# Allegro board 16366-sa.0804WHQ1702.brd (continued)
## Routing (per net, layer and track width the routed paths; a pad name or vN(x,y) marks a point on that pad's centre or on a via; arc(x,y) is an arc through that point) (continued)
P3V3_PG: length 102.1
  TOP w0.178: U9.2 10.9,75.95 12.55,77.6 55.53,77.6 56.23,76.9 56.23,75.89 56.81,75.3 74.46,75.3 79.02,70.75 82.3,70.75 85.22,67.83 97.18,67.83 97.73,68.37 PR441.1 98.56,68.37 99.01,68.82 101.6,68.82 PR2172.2 PR347.2 103.95,68.86 104.67,68.14 PU54.3
P3V3_RF: length 5.1
  TOP w0.254: v2(112.25,73.26) 112.06,73.07 PR3.2 PR4.2 112.06,70.53 111.79,70.27 111.79,69.47 111.46,69.14 PU54.22
P3V3_ROVP: length 4.1
  TOP w0.254: PU54.5 104.89,67.14 v2(104.09,66.34) 102.71,64.96 PR817.1
P3V3_SNB: length 1.7
  TOP w0.254: PC918.2 108.4,60.09 PR642.1
P3V3_TRIP: length 3.9
  TOP w0.254: PR2.2 112.98,70.6 112.98,69.55 v2(112.82,69.4) 112.07,68.64 112.07,68.64 PU54.21
P3V3_VBST: length 3.7
  TOP w0.305: PU54.4 104.23,67.64 103.21,66.61 PR481.1
P3V3_VBST_RC: length 1.2
  TOP w0.508: PC917.1 PR481.2
P3V3_VDD: length 10.3
  TOP w0.305: PC941.1 v2(115.78,70.83) 114.93,69.98 114.93,69.63 112.93,67.64 PU54.19
  TOP w0.508: PR649.2 117.38,69.89 PC941.1
P3V3_VFB: length 10.1
  TOP w0.254: PU54.1 105.87,71.11 106.02,71.26 PR638.1 106.02,72.45 104.75,73.72 PR635.2 PC485.2
P3V3_VFB_R: length 3.2
  TOP w0.254: PR635.1 100.53,73.9 100.53,74.85 v2(100.38,75) 100.1,75 99.39,74.3 99.39,73.87 PR633.2
P3V3_VIN:
  vias: v2(114.72,64.33)
P3V3_VREG: length 34.5
  TOP w0.254: v1(114.89,68.41) 114.89,67.8 PC942.2 114.22,67.14 PU54.18 ; PR441.2 99.01,67.48 v1(99.63,68.1) ; PR3.1 111.17,73 v1(111.18,73.01)
  BOTTOM w0.254: v1(111.18,73.01) 111.51,73.34 113.55,73.34 v2(115.38,71.51) 116.42,70.47 116.42,69.15 115.68,68.41 v1(114.89,68.41) 110.85,68.41 110.34,67.91 105.85,67.91 104.02,66.08 101.65,66.08 v1(99.63,68.1)
P12V: length 91.5
  TOP w0.457: CN2.B1 22.09,51.86 ; CN2.B1 22.98,50.98 ; CN2.B1 21.2,50.98 ; CN2.B1 22.09,50.09 ; CN4.4 119.9,48.24 ; CN4.4 118.26,46.6 ; CN4.4 119.9,44.96 ; CN4.4 121.54,46.6 ; CN3.B2 23.98,69.98 ; CN3.B2 22.2,69.98 ; CN3.B2 23.09,70.86 ; CN3.B2 23.09,69.09 ; CN2.A3 24.98,53.48 ; CN2.A3 23.2,53.48 ; CN2.A3 24.09,52.59 ; CN2.A3 24.09,54.36 ; 24.09,71.09 CN3.B3 ; CN3.B3 23.2,71.98 ; CN3.B3 24.09,72.86 ; CN3.B3 24.98,71.98 ; 119.9,49.16 CN4.3 ; CN4.3 119.9,52.44 ; CN4.3 118.26,50.8 ; CN4.3 121.54,50.8 ; 22.09,71.09 CN3.B1 ; CN3.B1 22.09,72.86 ; CN3.B1 22.98,71.98 ; CN3.B1 21.2,71.98 ; CN2.A2 23.98,55.48 ; CN2.A2 22.2,55.48 ; CN2.A2 23.09,56.36 ; CN2.A2 23.09,54.59 ; CN2.B2 23.09,49.86 ; CN2.B2 23.98,48.98 ; CN2.B2 23.09,48.09 ; CN2.B2 22.2,48.98 ; 23.2,50.98 CN2.B3 ; CN2.B3 24.98,50.98 ; CN2.B3 24.09,50.09 ; CN2.B3 24.09,51.86
  TOP w0.508: C23.1 17.47,68.11 R5.1
  L3 w0.457: 23.2,53.48 CN2.A3 ; CN2.A3 24.09,54.36 ; CN2.A3 24.98,53.48 ; CN2.A3 24.09,52.59 ; 23.09,69.09 CN3.B2 ; CN3.B2 23.09,70.86 ; CN3.B2 23.98,69.98 ; CN3.B2 22.2,69.98 ; 24.09,50.09 CN2.B3 ; CN2.B3 24.09,51.86 ; CN2.B3 24.98,50.98 ; CN2.B3 23.2,50.98 ; CN2.A2 23.98,55.48 ; CN2.A2 22.2,55.48 ; CN2.A2 23.09,54.59 ; CN2.A2 23.09,56.36 ; CN3.A3 24.09,75.36 ; CN3.A3 23.2,74.48 ; CN3.A3 24.09,73.59 ; CN3.A3 24.98,74.48 ; CN3.A2 23.98,76.48 ; CN3.A2 23.09,75.59 ; CN3.A2 22.2,76.48 ; CN3.A2 23.09,77.36 ; 23.2,71.98 CN3.B3 ; CN3.B3 24.98,71.98 ; CN3.B3 24.09,71.09 ; CN3.B3 24.09,72.86 ; CN4.4 121.54,46.6 ; CN4.4 118.26,46.6 ; CN4.4 119.9,44.96 ; CN4.4 119.9,48.24 ; CN2.B2 23.98,48.98 ; CN2.B2 23.09,49.86 ; CN2.B2 22.2,48.98 ; CN2.B2 23.09,48.09 ; 119.9,49.16 CN4.3 ; CN4.3 121.54,50.8 ; CN4.3 118.26,50.8 ; CN4.3 119.9,52.44 ; CN3.B1 22.09,72.86 ; CN3.B1 22.98,71.98 ; CN3.B1 22.09,71.09 ; CN3.B1 21.2,71.98 ; 21.2,50.98 CN2.B1 ; CN2.B1 22.09,50.09 ; CN2.B1 22.98,50.98 ; CN2.B1 22.09,51.86
  vias: v3(22.88,62.15) v3(22.85,59.17) v3(24.02,59.17) v3(24.2,62.12) v3(25.32,59.15) v3(25.52,62.12)
P12V_MB: length 20.2
  TOP w0.508: R1.1 18.17,15.49 C21.1 v1(16.99,15.43)
  L4 w0.457: 23.2,32.47 CN1.A3 ; CN1.A3 24.09,33.36 ; CN1.A3 24.09,31.59 ; CN1.A3 24.98,32.47 ; CN1.B1 22.09,30.86 ; CN1.B1 22.09,29.09 ; CN1.B1 21.2,29.98 ; CN1.B1 22.98,29.98 ; 23.09,33.59 CN1.A2 ; CN1.A2 22.2,34.47 ; CN1.A2 23.09,35.36 ; CN1.A2 23.98,34.47 ; CN1.B2 23.09,28.86 ; CN1.B2 23.98,27.98 ; CN1.B2 22.2,27.98 ; CN1.B2 23.09,27.09 ; 24.09,29.09 CN1.B3 ; CN1.B3 24.98,29.98 ; CN1.B3 24.09,30.86 ; CN1.B3 23.2,29.98
  vias: v1(17.27,29.9) v1(18.22,34.43) v1(18.22,33.37) v1(18.22,32.33) v1(18.22,30.83) v3(13.18,8.42) v3(13.2,7.28) v3(14.27,8.41) v3(14.32,7.29)
ADDR_0: length 3.9
  TOP w0.178: R29.1 9.18,42.59 R28.2 9.16,44.64 U10.1
ADDR_1: length 6.1
  TOP w0.178: R30.1 8.1,42.59 R27.2 7.06,44.31 8.61,45.85 U10.2
ADDR_2: length 3.7
  TOP w0.178: R26.2 R31.1 11.8,45.38 10.68,46.5 U10.3
CLK100_PCIE_SLOT0_N: length 34.3
  BOTTOM w0.178: CN1.A14 36.74,33.77 36.82,33.53 36.91,33.49 37.02,33.43 37.33,33.12 37.33,29.53 36.34,28.54 36.34,27.15 32.41,21.55 28.47,11.97 26.92,7.45 26.63,6.68 26.37,6.42 26.37,6.12 26.65,5.83 GF1.A14
CLK100_PCIE_SLOT0_P: length 34.3
  BOTTOM w0.178: GF1.A13 25.65,5.67 26.06,6.08 26.06,6.55 26.37,6.85 26.64,7.55 28.19,12.08 30.76,18.34 30.66,18.58 30.87,19.07 31.1,19.17 31.31,19.67 31.21,19.9 31.41,20.4 31.65,20.5 32.14,21.69 32.16,21.72 36.03,27.25 36.03,28.67 37.02,29.66 37.02,33 36.84,33.18 36.68,33.26 36.44,33.18 CN1.A13
CLK100_PCIE_SLOT1_N: length 67.6
  BOTTOM w0.178: GF1.A33 45.65,5.85 45.25,6.25 45.25,7.58 51.29,19.75 56.23,26.79 56.23,28.47 57.24,29.48 57.24,32.99 56.23,34 56.23,35.04 55.78,35.57 52.45,37.8 46.61,43.9 45.92,46.39 44.49,47.82 40.76,47.82 40.25,48.33 40.25,49.52 39.67,50.11 37.69,50.11 37.25,50.54 37.25,54.2 37.02,54.43 36.82,54.53 36.74,54.77 CN2.A14
CLK100_PCIE_SLOT1_P: length 67.6
  BOTTOM w0.178: CN2.A13 36.44,54.18 36.68,54.26 36.8,54.2 36.84,54.18 36.95,54.07 36.95,50.41 37.56,49.8 39.54,49.8 39.95,49.4 39.95,48.2 40.63,47.52 44.36,47.52 45.65,46.23 46.34,43.74 47.3,42.73 47.96,42.05 48.33,41.66 48.99,40.97 52.25,37.57 55.57,35.34 55.92,34.93 55.92,33.88 56.94,32.86 56.94,29.61 55.92,28.59 55.92,26.89 54.46,24.8 54.28,24.77 53.98,24.33 54.01,24.16 53.7,23.72 53.53,23.69 53.5,23.69 53.22,23.29 53.22,23.25 53.25,23.08 52.95,22.64 52.73,22.64 52.47,22.27 52.47,22.17 52.5,22 51.04,19.92 51.03,19.9 44.95,7.65 44.95,6.25 44.65,5.95 GF1.A32
CLK100_PCIE_SLOT2_N: length 88.9
  BOTTOM w0.178: GF1.A6 16.65,5.92 16.35,6.22 16.35,7.62 18.26,15.88 20.68,25.18 20.68,25.21 20.78,28.19 19.02,38.17 19.54,41.14 21.01,43.24 21.54,43.61 21.86,43.83 24.4,44.28 26.2,46.08 26.2,49.22 27.25,50.26 27.25,53.92 28.19,54.86 28.19,55.87 29.26,56.94 32.52,57.52 35.54,56.99 38.31,57.47 39.03,57.98 39.45,58.58 39.5,58.84 39.53,59.02 39.58,59.33 39.81,60.61 38.59,67.51 38.24,69.49 38.24,70.63 37.3,71.57 37.3,75.15 37.02,75.43 36.82,75.53 36.74,75.77 CN3.A14
CLK100_PCIE_SLOT2_P: length 88.9
  BOTTOM w0.178: CN3.A13 36.44,75.18 36.68,75.26 36.84,75.18 37,75.02 37,71.44 37.94,70.5 37.94,69.46 38.71,65.08 38.57,64.87 38.66,64.35 38.87,64.2 38.96,63.68 38.81,63.47 38.91,62.94 39.11,62.8 39.5,60.61 39.28,59.38 39.23,59.08 39.2,58.9 39.16,58.7 38.81,58.2 38.5,57.98 38.19,57.76 35.54,57.3 32.52,57.83 29.11,57.23 27.88,56 27.88,54.98 26.94,54.04 26.94,50.39 25.9,49.34 25.9,46.21 24.25,44.56 21.74,44.12 21.52,43.97 20.79,43.46 19.29,41.31 19.24,41.26 19.24,41.19 18.71,38.17 20.47,28.16 20.38,25.26 17.97,15.96 16.05,7.66 16.05,6.23 15.65,5.83 GF1.A5
INTRPT: length 5.7
  TOP w0.178: U10.17 5.03,47.15 5.23,46.95 5.23,42.95 R17.1
INTRPT_0: length 2.5
  TOP w0.178: R13.1 11.19,47.15 U10.4
INTRPT_1: length 6.2
  TOP w0.178: U10.7 8.84,49.1 8.41,49.54 8.41,51.42 8.79,51.8 9.37,51.8 10.02,52.45 R14.1
INTRPT_2: length 1.3
  TOP w0.178: R15.1 4.08,52.3 U10.11
INTRPT_3: length 7.9
  TOP w0.178: U10.14 5.19,49.1 5.97,48.32 R16.1
LAN_SMB_ALERT_N: length 71.9
  TOP w0.178: RE11.2 41.32,61.95 41.32,58.93 38.13,55.74 38.13,54.99 37.23,54.09 37.23,53.28 34.25,50.31 34.25,47.57 35.89,45.93 RE5.2 35.89,42.52 36.16,42.26 36.16,33.82 37.13,32.84 37.13,29.66 36.17,28.69 36.17,24.63 RE4.2 35.98,21.53 24.88,10.44 24.88,6.4 24.65,6.17 GF1.B12
LAN_SMB_CLK: length 99.1
  TOP w0.178: RE2.1 38.83,38.31 v1(38.83,39.24) 38.83,39.34 38.78,39.39 RE9.1 ; v1(18.79,8.82) 18.79,8.13 19.65,7.27 GF1.B9 ; RE14.1 43.93,57.64 43.93,57.43 43.93,57.06 44.47,56.53 55.41,56.53 55.86,56.08 55.86,54.89 56.84,53.91 56.84,53.16 56.11,52.44 45.8,52.44 44.87,51.5 44.87,50.51 43.85,49.49 43.85,46.67 v1(43.65,46.47)
  BOTTOM w0.178: v1(18.79,8.82) 18.79,9.3 19.09,9.6 19.09,13.66 23.9,18.47 23.9,28.33 22.89,29.34 22.89,33.05 23.9,34.07 23.9,35.26 24.51,35.87 36.96,35.87 39.13,38.04 39.13,38.93 v1(38.83,39.24) 39.17,39.58 39.17,40.34 43.37,44.54 ; 43.37,44.54 v2(43.11,44.8) ; 43.37,44.54 43.96,45.13 43.96,46.17 v1(43.65,46.47)
LAN_SMB_DAT: length 99.4
  TOP w0.178: RE10.1 39.92,39.36 v1(39.84,39.29) 39.82,39.26 RE3.1 ; v1(44.57,46.47) 44.28,46.76 44.28,49.31 45.31,50.33 45.31,51.33 45.98,52 56.29,52 57.27,52.99 57.27,54.09 56.3,55.07 56.3,56.26 55.59,56.96 44.64,56.96 44.37,57.24 44.37,57.61 RE15.1
  BOTTOM w0.178: 41.18,41.74 v2(41.42,41.51) ; 41.18,41.74 44.39,44.95 44.39,46.29 v1(44.57,46.47) ; 41.18,41.74 39.6,40.16 39.6,39.53 v1(39.84,39.29) 39.56,39.01 39.56,37.86 37.14,35.44 24.69,35.44 24.33,35.08 24.33,33.89 23.32,32.87 23.32,29.52 24.33,28.51 24.33,18.29 19.52,13.49 19.52,8.51 18.39,7.38 18.39,6.06 18.65,5.81 GF1.A8
PCH_PLTRST_N: length 42.5
  TOP w0.178: v1(25.02,31.55) 25.04,31.58 25.04,33.08 24.54,33.59 22.58,33.59 20.29,35.87 17.83,35.87 17.02,36.68 U13.2
  BOTTOM w0.178: v1(25.02,31.55) 25.04,31.53 25.04,29.42 26.09,28.38 26.09,14.87 21.54,10.32 21.54,6.77 21.65,6.67 GF1.A11
PCIE_SLOT0_CPRSNT1_N: length 45.1
  TOP w0.178: CN1.B31 54.09,30.3 53.48,30.9 41.02,30.9 CN1.B17 40.09,28.73 40.23,28.59 40.23,23.28 40.2,23.12 39.14,19.06 36.96,16.16 29.65,8.86 GF1.B17
PCIE_SLOT0_CPRSNT2_N: length 51.3
  TOP w0.178: CN1.B48 71.04,28.03 71.04,30.75 70.78,31.01 55.31,31.01 55.11,30.8 55.11,29.1 54.86,28.85 52.57,28.85 51.96,28.24 51.96,25.67 51.59,25.3 51.59,20.7 43.26,6.94 43.26,6.27 43.65,5.88 GF1.B31
PCIE_SLOT0_RXN0: length 34.9
  BOTTOM w0.178: GF1.A17 29.65,5.83 29.28,6.2 29.28,7.6 30.71,11.49 35.2,19.67 35.88,20.53 36.14,20.56 36.47,20.98 36.44,21.24 36.77,21.66 37.03,21.69 37.36,22.11 37.33,22.37 39.74,25.42 39.92,25.87 39.93,25.87 40.2,27.41 40.2,28.52 39.23,29.48 39.23,33.07 39.34,33.18 39.5,33.26 39.74,33.18 CN1.A17
PCIE_SLOT0_RXN1: length 34.4
  BOTTOM w0.178: GF1.A22 34.65,5.93 34.36,6.22 34.36,7.6 39.39,18.24 43.76,24.48 44.34,27.73 44.34,27.73 44.34,28.29 45.31,29.41 45.31,33.15 45.02,33.43 44.82,33.53 44.74,33.77 CN1.A22
PCIE_SLOT0_RXN2: length 34.5
  BOTTOM w0.178: GF1.A26 38.65,5.87 38.33,6.19 38.33,7.63 42.92,17.72 43.28,18.24 44.24,19.61 44.24,19.61 47.72,24.57 48.18,27.17 48.18,28.34 49.32,29.48 49.32,33.13 49.02,33.43 48.82,33.53 48.74,33.77 CN1.A26
PCIE_SLOT0_RXN3: length 34.4
  BOTTOM w0.178: CN1.A30 52.74,33.77 52.82,33.53 53.02,33.43 53.26,33.2 53.26,29.38 52.32,28.44 52.32,26.92 52.08,25.57 48.28,20.14 42.35,7.53 42.35,6.2 42.65,5.91 GF1.A30
PCIE_SLOT0_RXN4: length 34.5
  BOTTOM w0.178: CN1.A36 58.74,33.77 58.82,33.53 59.02,33.43 59.28,33.18 59.28,29.48 58.31,28.52 58.31,26.28 58.2,25.68 56.71,23.54 53.66,19.19 48.33,7.78 48.33,6.15 48.65,5.83 GF1.A36
PCIE_SLOT0_RXN5: length 34.5
  BOTTOM w0.178: CN1.A40 62.74,33.77 62.82,33.53 63.02,33.43 63.26,33.19 63.26,29.46 62.3,28.49 62.3,26.66 62.16,25.86 61.88,25.47 58.6,20.79 56.26,17.45 52.33,7.73 52.33,6.15 52.65,5.83 GF1.A40
PCIE_SLOT0_RXN6: length 34.4
  BOTTOM w0.178: CN1.A44 66.74,33.77 66.82,33.53 67.02,33.43 67.28,33.17 67.28,29.53 66.29,28.54 66.29,26.81 66.09,25.84 60.48,17.43 56.33,7.68 56.33,6.15 56.65,5.83 GF1.A44
PCIE_SLOT0_RXN7: length 34.6
  BOTTOM w0.178: GF1.A48 60.65,5.83 60.33,6.15 60.33,7.65 63.3,15.98 64.89,18.24 67.47,21.92 70.13,25.72 70.25,26.41 70.25,28.39 71.34,29.48 71.34,33.11 71.02,33.43 70.82,33.53 70.74,33.77 CN1.A48
PCIE_SLOT0_RXP0: length 34.9
  BOTTOM w0.178: GF1.A16 28.65,5.83 28.97,6.15 28.97,7.66 30.42,11.59 30.43,11.62 34.95,19.84 39.47,25.58 39.64,25.98 39.64,25.99 39.64,25.99 39.9,27.43 39.9,28.39 38.93,29.36 38.93,33.2 39.07,33.34 39.16,33.43 39.36,33.53 39.44,33.77 CN1.A16
PCIE_SLOT0_RXP1: length 34.4
  BOTTOM w0.178: CN1.A21 44.44,33.18 44.68,33.26 44.84,33.18 45,33.02 45,29.52 44.04,28.4 44.04,27.78 43.47,24.6 42.93,23.82 42.75,23.79 42.45,23.35 42.48,23.18 42.17,22.74 42,22.71 41.69,22.27 41.72,22.1 41.42,21.66 41.24,21.63 40.94,21.19 40.97,21.02 39.14,18.41 39.13,18.39 34.05,7.67 34.05,6.23 33.65,5.83 GF1.A21
PCIE_SLOT0_RXP2: length 34.5
  BOTTOM w0.178: GF1.A25 37.65,5.83 38.02,6.2 38.02,7.69 42.65,17.87 43.03,18.41 43.99,19.78 44.98,21.19 44.95,21.36 45.25,21.8 45.42,21.83 45.73,22.27 45.7,22.44 46.01,22.88 46.18,22.91 46.49,23.35 46.45,23.52 46.76,23.96 46.93,23.99 47.24,24.42 47.24,24.42 47.43,24.69 47.67,26.08 47.77,26.64 47.87,27.2 47.87,28.47 49.01,29.61 49.01,33.01 48.84,33.18 48.68,33.26 48.44,33.18 CN1.A25
PCIE_SLOT0_RXP3: length 34.4
  BOTTOM w0.178: GF1.A29 41.65,5.8 42.05,6.19 42.05,7.59 48.01,20.3 48.03,20.32 48.82,21.45 48.79,21.63 49.1,22.06 49.27,22.09 49.58,22.53 49.55,22.7 49.85,23.14 50.03,23.17 50.33,23.61 50.3,23.78 50.61,24.22 50.78,24.25 51.79,25.69 52.01,26.94 52.01,28.57 52.95,29.51 52.95,33.07 52.84,33.18 52.68,33.26 52.44,33.18 CN1.A29
PCIE_SLOT0_RXP4: length 34.4
  BOTTOM w0.178: GF1.A35 47.65,5.83 48.02,6.2 48.02,7.85 53.4,19.34 53.41,19.37 54.5,20.91 54.47,21.09 54.77,21.52 54.94,21.55 55.25,21.99 55.22,22.16 55.53,22.6 55.7,22.63 56.01,23.07 55.97,23.24 56.28,23.68 56.45,23.71 57.92,25.8 58.01,26.31 58.01,28.64 58.97,29.61 58.97,33.05 58.84,33.18 58.68,33.26 58.44,33.18 CN1.A35
PCIE_SLOT0_RXP5: length 34.5
  BOTTOM w0.178: CN1.A39 62.44,33.18 62.68,33.26 62.84,33.18 62.96,33.06 62.96,29.58 61.99,28.62 61.99,26.69 61.87,25.98 61.63,25.64 61.28,25.15 61.11,25.12 60.8,24.68 60.84,24.51 60.53,24.07 60.36,24.04 60.05,23.6 60.08,23.43 59.77,22.99 59.6,22.96 59.3,22.53 59.33,22.35 58.35,20.97 56.57,18.41 56.01,17.62 55.99,17.59 52.02,7.79 52.02,6.2 51.65,5.83 GF1.A39
PCIE_SLOT0_RXP6: length 34.4
  BOTTOM w0.178: GF1.A43 55.65,5.83 56.02,6.2 56.02,7.74 60.21,17.58 63.64,22.72 63.58,23.01 63.88,23.45 64.17,23.51 64.46,23.95 64.41,24.24 64.7,24.68 64.99,24.74 65.8,25.96 65.98,26.84 65.98,28.67 66.97,29.66 66.97,33.05 66.84,33.18 66.68,33.26 66.44,33.18 CN1.A43
PCIE_SLOT0_RXP7: length 34.6
  BOTTOM w0.178: GF1.A47 59.65,5.83 60.02,6.2 60.02,7.71 63.03,16.12 64.64,18.41 66.68,21.34 66.68,21.34 67.32,22.24 67.29,22.41 67.59,22.85 67.77,22.88 68.07,23.32 68.04,23.49 68.35,23.93 68.52,23.96 68.83,24.4 68.8,24.57 69.1,25.01 69.27,25.04 69.71,25.66 69.84,25.84 69.94,26.43 69.94,28.52 71.04,29.61 71.04,32.98 70.84,33.18 70.68,33.26 70.44,33.18 CN1.A47
PCIE_SLOT0_TXN0: length 30.5
  TOP w0.178: CN1.B15 37.74,29.27 37.82,29.03 38.02,28.93 38.27,28.68 38.27,26.18 37.87,21.04 37.19,19.9 30.76,13.57 27.35,7.55 27.35,6.19 27.65,5.9 GF1.B15
PCIE_SLOT0_TXN1: length 30
  TOP w0.178: CN1.B20 43.09,28.37 42.7,28.76 42.44,28.76 42.17,28.49 42.17,26.23 42.16,26.23 42.08,25.77 41.73,21.46 40.17,16.33 40.16,16.31 39.15,14.03 38.32,12.84 37.82,12.12 33.45,9.06 32.79,8.12 32.33,7.46 32.3,7.32 32.3,6.28 32.65,5.93 GF1.B20
PCIE_SLOT0_TXN2: length 29.8
  TOP w0.178: GF1.B24 36.65,5.93 36.29,6.29 36.29,7.96 36.77,8.64 40.34,11.15 43.81,16.16 43.85,16.21 45.45,22.23 46.22,26.59 46.22,28.53 46.4,28.71 46.79,28.71 47.09,28.41 CN1.B24
PCIE_SLOT0_TXN3: length 29
  TOP w0.178: CN1.B28 50.74,28.68 50.5,28.76 50.34,28.68 50.26,28.6 50.26,27.45 50.17,26.92 50.27,26.78 50.17,26.25 50.03,26.15 49.84,25.08 49.83,25.07 49.77,24.91 47.02,17.69 47,17.66 44.84,14.18 40.3,7.71 40.3,6.28 40.65,5.93 GF1.B28
PCIE_SLOT0_TXN4: length 29.2
  TOP w0.178: GF1.B34 46.65,5.83 46.3,6.18 46.3,7.48 49.2,12.66 51.24,15.62 52.84,18.66 53.13,18.75 53.37,19.22 53.29,19.5 53.54,19.98 53.82,20.06 54.07,20.54 53.98,20.82 55.63,23.95 55.71,24.13 55.71,24.13 56.2,26.91 56.2,28.54 56.34,28.68 56.5,28.76 56.74,28.68 CN1.B34
PCIE_SLOT0_TXN5: length 29.2
  TOP w0.178: GF1.B38 50.65,5.83 50.25,6.23 50.25,7.25 52.5,12.17 54.23,14.61 55.9,17.58 56.17,17.65 56.43,18.12 56.36,18.38 56.62,18.85 56.89,18.92 57.15,19.39 57.08,19.65 59.73,24.35 59.73,24.37 59.92,24.8 59.92,24.81 59.92,24.81 60.22,26.46 60.22,28.55 60.34,28.68 60.5,28.76 60.74,28.68 CN1.B38
PCIE_SLOT0_TXN6: length 29.2
  TOP w0.178: CN1.B42 64.74,28.68 64.5,28.76 64.34,28.68 64.25,28.59 64.25,26.98 63.91,25.02 63.9,25.01 63.72,24.57 60.9,19.55 60.98,19.24 60.72,18.78 60.42,18.7 60.16,18.23 60.24,17.93 59.98,17.46 59.68,17.38 57.71,13.88 55.96,11.59 54.35,7.62 54.35,6.17 54.65,5.87 GF1.B42
PCIE_SLOT0_TXN7: length 29.2
  TOP w0.178: GF1.B46 58.65,5.91 58.27,6.29 58.27,7.55 58.83,10.5 62.89,18.27 63.67,19.61 63.94,19.68 64.21,20.14 64.14,20.41 64.41,20.88 64.68,20.95 64.95,21.41 64.88,21.68 68.22,27.4 68.22,28.56 68.34,28.68 68.5,28.76 68.74,28.68 CN1.B46
PCIE_SLOT0_TXP0: length 30.5
  TOP w0.178: CN1.B14 37.44,28.68 37.68,28.76 37.84,28.68 37.9,28.62 37.96,28.56 37.96,26.2 37.57,21.13 36.94,20.09 30.52,13.76 30.49,13.72 30.15,13.12 29.7,12.33 29.44,11.86 29.18,11.79 28.92,11.32 28.99,11.07 28.73,10.6 28.47,10.53 28.21,10.07 28.28,9.81 27.05,7.63 27.05,6.23 26.65,5.83 GF1.B14
PCIE_SLOT0_TXP1: length 30
  TOP w0.178: GF1.B19 31.65,5.93 32,6.28 32,7.34 32.04,7.58 32.54,8.29 32.87,8.77 33.23,9.28 37.6,12.34 38.89,14.18 39.88,16.42 41.43,21.52 41.78,25.81 41.86,26.28 41.86,28.61 42.09,28.84 CN1.B19
PCIE_SLOT0_TXP2: length 29.8
  TOP w0.178: GF1.B23 35.65,5.93 35.98,6.27 35.98,8.06 36.55,8.86 40.12,11.36 43.56,16.34 45.15,22.3 45.91,26.62 45.91,28.65 46.09,28.83 CN1.B23
PCIE_SLOT0_TXP3: length 29
  TOP w0.178: GF1.B27 39.65,5.93 40,6.28 40,7.8 44.58,14.35 46.73,17.79 49.48,25.02 49.55,25.19 49.55,25.2 49.95,27.48 49.95,28.72 50.09,28.86 CN1.B27
PCIE_SLOT0_TXP4: length 29.2
  TOP w0.178: GF1.B33 45.65,5.83 46,6.18 46,7.55 48.94,12.82 48.95,12.83 50.98,15.78 55.35,24.07 55.42,24.24 55.42,24.25 55.9,26.94 55.9,28.67 56.16,28.93 56.36,29.03 56.44,29.27 CN1.B33
PCIE_SLOT0_TXP5: length 29.2
  TOP w0.178: CN1.B37 60.44,29.27 60.36,29.03 60.16,28.93 59.91,28.68 59.91,26.49 59.64,24.93 59.64,24.93 59.63,24.92 59.45,24.49 53.97,14.78 52.25,12.35 52.24,12.33 49.95,7.32 49.95,6.13 49.65,5.83 GF1.B37
PCIE_SLOT0_TXP6: length 29.2
  TOP w0.178: GF1.B41 53.65,5.83 54.05,6.23 54.05,7.68 55.67,11.7 55.69,11.74 57.45,14.04 63.44,24.7 63.62,25.13 63.62,25.13 63.95,27.01 63.95,28.72 64.16,28.93 64.36,29.03 64.44,29.27 CN1.B41
PCIE_SLOT0_TXP7: length 29.2
  TOP w0.178: GF1.B45 57.65,6 57.97,6.31 57.97,7.58 58.54,10.6 62.62,18.42 67.91,27.48 67.91,28.68 68.16,28.93 68.36,29.03 68.44,29.27 CN1.B45
PCIE_SLOT1_CPRSNT1_N: length 102.6
  TOP w0.178: CN2.B17 40.09,50.98 40.81,50.98 42.73,52.9 v1(43.1,52.9) ; GF1.B48 60.65,8.05 60.81,8.94 64.48,14.18 68.63,18.33 68.63,23.27 75.6,30.25 75.6,32.2 74.23,33.57 60.65,33.57 60.09,34.14 60.09,34.78 59.39,35.48 v1(58.28,35.48)
  BOTTOM w0.178: v1(43.1,52.9) 43.1,53.94 44.07,54.91 44.07,56.01 44.47,56.41 53.62,56.41 54.14,55.88 54.14,54.78 55.01,53.92 55.01,52.24 54.09,51.32 CN2.B31 54.09,50.98 ; CN2.B17 40.14,50.98 41.14,49.98 45.48,49.98 46.3,49.16 46.3,47.01 57.83,35.48 v1(58.28,35.48)
PCIE_SLOT1_CPRSNT2_N: length 56.4
  TOP w0.178: GF1.B81 93.65,8.5 92.1,18.39 91.63,20.9 88.8,36.98 88.7,37.5 85.47,42.11 84.23,43.88 79.57,47.15 77.11,47.78 72.54,48.98 71.09,48.98 CN2.B48
PCIE_SLOT1_RXN0: length 80.6
  BOTTOM w0.178: CN2.A17 39.74,54.18 39.5,54.26 39.34,54.18 39.23,54.07 39.23,53.05 40.17,52.11 46.5,52.11 47.31,51.3 47.31,50.39 48.28,49.42 48.28,47.36 55.07,40.57 55.51,40.27 55.68,40.3 56.12,39.99 56.15,39.82 56.58,39.51 56.76,39.54 57.19,39.24 57.22,39.06 58.51,38.16 59.04,38.07 59.18,38.17 59.71,38.07 59.81,37.93 60.34,37.84 61.62,37.61 62.92,37.38 63.65,37.25 66.85,36.69 67.66,36.55 72.86,35.63 74.66,34.37 75.27,33.5 75.89,32.62 76.14,31.17 75.18,25.73 72.77,18.91 72.75,18.88 65.25,7.58 65.25,6.27 65.65,5.87 GF1.A53
PCIE_SLOT1_RXN1: length 76
  BOTTOM w0.178: GF1.A57 69.65,5.86 69.33,6.18 69.33,7.42 75.03,18.52 75.04,18.55 76.53,23.27 78.02,31.68 77.58,34.17 76.92,35.11 74.47,36.82 60.92,39.21 59.59,40.15 52.57,45.06 50.33,48.25 50.33,49.32 49.27,50.39 49.27,51.53 48.48,52.32 47.87,52.32 47.21,52.98 47.21,54.2 46.68,54.73 45.64,54.73 45.31,54.39 45.06,54.39 45.02,54.43 44.82,54.53 44.74,54.77 CN2.A22
PCIE_SLOT1_RXN2: length 72.6
  BOTTOM w0.178: GF1.A61 73.65,5.87 73.33,6.19 73.33,7.68 77.15,18.24 79.5,31.52 78.92,34.76 77.91,36.21 76.41,37.26 74.9,38.32 68.12,39.51 61.48,40.68 54.34,45.68 52.29,47.73 52.29,49.55 51.33,50.51 51.33,51.45 50.41,52.37 49.98,52.37 49.27,53.08 49.27,54.18 49.12,54.33 49.02,54.43 48.82,54.53 48.74,54.77 CN2.A26
PCIE_SLOT1_RXN3: length 70.9
  BOTTOM w0.178: CN2.A30 52.74,54.77 52.82,54.53 53.02,54.43 53.31,54.14 53.31,50.61 54.14,49.65 54.14,48.56 54.73,47.97 56.02,47.97 58.76,45.24 59.73,43.84 61.73,42.45 62.37,42 75.63,39.66 78.83,37.42 80.29,35.34 81.41,28.79 81.42,28.73 78.52,14.07 77.33,7.39 77.33,6.15 77.65,5.83 GF1.A65
PCIE_SLOT1_RXN4: length 67.4
  BOTTOM w0.178: CN2.A36 58.74,54.77 58.82,54.53 59.02,54.43 59.28,54.18 59.28,50.59 60.22,49.65 60.22,48.18 60.51,46.5 61.47,45.13 62.11,44.49 65.73,43.01 66.23,42.95 67.01,42.82 76.17,41.2 79.76,38.68 80.75,37.27 81.11,36.75 81.19,36.65 81.75,35.85 83.34,26.32 83.34,26.28 81.33,7.57 81.33,6.19 81.65,5.87 GF1.A69
PCIE_SLOT1_RXN5: length 65.3
  BOTTOM w0.178: CN2.A40 62.74,54.77 62.82,54.53 63.02,54.43 63.29,54.16 63.29,50.56 64.28,49.57 64.28,48.3 64.48,47.19 65.83,45.25 67.12,44.35 76.72,42.66 81.27,39.47 83.26,36.64 86.28,18.09 85.34,7.82 85.34,6.22 85.65,5.91 GF1.A73
PCIE_SLOT1_RXN6: length 63.7
  BOTTOM w0.178: GF1.A77 89.65,5.83 89.33,6.15 89.33,7.87 89,13.32 88.62,15.94 88.24,18.55 84.78,37.41 82.92,40.07 76.93,44.27 69.39,45.6 69.02,45.85 68.32,46.85 68.22,47.47 68.22,49.6 67.25,50.56 67.25,54.2 67.02,54.43 66.82,54.53 66.74,54.77 CN2.A44
PCIE_SLOT1_RXN7: length 60.6
  BOTTOM w0.178: CN2.A48 70.74,54.77 70.82,54.53 71.02,54.43 71.29,54.16 71.29,50.61 72.31,49.6 73.04,48.86 83.78,41.32 86.41,37.98 89.89,19.01 92.08,14.18 93.24,7.6 93.33,7.08 93.33,6.18 93.65,5.86 GF1.A81
PCIE_SLOT1_RXP0: length 80.6
  BOTTOM w0.178: CN2.A16 39.44,54.77 39.36,54.53 39.16,54.43 38.93,54.2 38.93,52.93 40.05,51.81 46.37,51.81 47.01,51.17 47.01,50.26 47.97,49.29 47.97,47.24 54.87,40.34 58.4,37.87 61.57,37.31 62.62,37.13 63.72,36.93 67.61,36.25 72.74,35.34 73.59,34.75 74.41,34.17 74.44,34.15 75.6,32.5 75.83,31.17 74.89,25.81 72.49,19.05 64.95,7.67 64.95,6.21 64.65,5.91 GF1.A52
PCIE_SLOT1_RXP1: length 76
  BOTTOM w0.178: CN2.A21 44.44,54.18 44.68,54.26 44.84,54.18 44.93,54.09 45.43,54.09 45.77,54.42 46.55,54.42 46.91,54.07 46.91,52.85 47.74,52.01 48.35,52.01 48.96,51.4 48.96,50.26 50.03,49.19 50.03,48.16 52.35,44.84 52.66,44.62 53.04,44.36 53.2,44.24 53.38,44.12 53.42,43.94 53.85,43.64 54.03,43.67 54.46,43.36 54.49,43.19 54.93,42.88 55.1,42.91 55.54,42.61 55.57,42.43 56.01,42.13 56.18,42.16 56.62,41.85 57.62,41.15 60.8,38.92 74.36,36.53 76.7,34.89 77.29,34.05 77.71,31.68 76.24,23.34 74.76,18.66 69.02,7.5 69.02,6.2 68.65,5.83 GF1.A56
PCIE_SLOT1_RXP2: length 72.6
  BOTTOM w0.178: CN2.A25 48.44,54.18 48.68,54.26 48.84,54.18 48.96,54.06 48.96,52.95 49.85,52.06 50.28,52.06 51.02,51.33 51.02,50.39 51.99,49.42 51.99,47.61 54.15,45.45 55.31,44.63 55.34,44.46 55.78,44.15 55.95,44.18 56.39,43.88 56.42,43.7 56.86,43.4 57.03,43.43 57.47,43.12 57.5,42.95 57.93,42.64 58.11,42.67 61.36,40.4 74.78,38.03 77.69,35.99 78.64,34.64 79.19,31.52 76.86,18.32 73.02,7.73 73.02,6.2 72.65,5.83 GF1.A60
PCIE_SLOT1_RXP3: length 70.8
  BOTTOM w0.178: GF1.A64 76.65,5.83 77.02,6.2 77.02,7.42 78.23,14.13 81.11,28.73 80,35.22 78.61,37.21 75.51,39.37 62.25,41.71 61.67,42.12 61.5,42.09 61.06,42.39 61.03,42.56 60.59,42.87 60.42,42.84 59.98,43.15 59.95,43.32 59.52,43.63 58.52,45.04 58.04,45.53 57.86,45.53 57.48,45.91 57.48,46.08 55.9,47.67 54.6,47.67 53.84,48.43 53.84,49.53 53,50.5 53,54.02 52.84,54.18 52.68,54.26 52.44,54.18 CN2.A29
PCIE_SLOT1_RXP4: length 67.4
  BOTTOM w0.178: CN2.A35 58.44,54.18 58.68,54.26 58.84,54.18 58.97,54.05 58.97,50.46 59.91,49.52 59.91,48.15 60.22,46.38 61.23,44.93 61.94,44.23 65.65,42.72 66.19,42.65 66.83,42.54 66.93,42.39 67.45,42.3 67.6,42.4 68.12,42.31 68.23,42.16 68.75,42.07 68.89,42.17 69.42,42.08 69.52,41.94 70.05,41.84 70.19,41.94 76.05,40.91 79.54,38.46 80.86,36.58 80.94,36.47 81.46,35.73 83.04,26.27 81.02,7.59 81.02,7.58 81.02,6.2 80.65,5.83 GF1.A68
PCIE_SLOT1_RXP5: length 65.3
  BOTTOM w0.178: GF1.A72 84.65,5.83 85.04,6.22 85.04,7.84 85.98,18.08 82.97,36.52 82.6,37.04 82.01,37.88 81.53,38.57 81.05,39.25 76.6,42.37 71.71,43.23 71.57,43.13 71.04,43.22 70.94,43.37 70.42,43.46 70.27,43.36 69.75,43.45 69.65,43.6 69.12,43.69 68.98,43.59 68.45,43.68 68.35,43.82 67,44.06 65.61,45.03 64.19,47.07 63.97,48.28 63.97,49.45 62.98,50.44 62.98,54.04 62.84,54.18 62.68,54.26 62.44,54.18 CN2.A39
PCIE_SLOT1_RXP6: length 63.6
  BOTTOM w0.178: CN2.A43 66.44,54.18 66.68,54.26 66.84,54.18 66.95,54.07 66.95,50.44 67.91,49.47 67.91,47.44 68.04,46.73 68.8,45.64 69.27,45.31 70.95,45.01 71.05,44.87 71.58,44.77 71.72,44.87 72.25,44.78 72.35,44.64 72.88,44.55 73.02,44.65 73.55,44.55 73.65,44.41 74.17,44.32 74.32,44.42 76.81,43.98 82.7,39.86 84.49,37.29 87.94,18.5 88.32,15.89 88.7,13.29 89.02,7.85 89.02,6.2 88.65,5.83 GF1.A76
PCIE_SLOT1_RXP7: length 60.6
  BOTTOM w0.178: CN2.A47 70.44,54.18 70.68,54.26 70.84,54.18 70.98,54.04 70.98,50.49 71.58,49.89 72.09,49.38 72.84,48.63 76.1,46.35 76.13,46.17 76.56,45.87 76.74,45.9 77.17,45.59 77.2,45.42 77.64,45.11 77.81,45.14 78.25,44.83 78.28,44.66 78.72,44.35 78.89,44.38 82.44,41.89 83.57,41.1 86.12,37.85 89.59,18.95 89.6,18.92 91.78,14.09 92.93,7.55 92.98,7.3 93.02,7.05 93.02,6.2 92.65,5.83 GF1.A80
PCIE_SLOT1_TXN0: length 82.7
  TOP w0.178: GF1.B51 63.65,6.02 63.34,6.33 63.34,7.37 63.83,8.24 67.85,11.49 67.89,11.52 70.24,13.59 70.26,13.62 75.31,20.84 77.92,30.46 77.92,30.94 77.92,30.95 77.71,32.15 76.36,34.07 73.76,35.9 70.22,36.52 66,35.93 65.06,35.93 46.88,39.13 40.71,43.45 40.07,44.36 40.07,45.8 38.27,47.61 38.27,49.68 38.02,49.93 37.82,50.03 37.74,50.27 CN2.B15
PCIE_SLOT1_TXN1: length 79.1
  TOP w0.178: GF1.B55 67.65,6.08 67.35,6.38 67.35,7.63 68.43,8.95 72.42,12.3 77.09,19.92 78.61,26.91 78.68,27.07 78.68,27.07 79.43,30.22 79.42,30.28 78.98,32.8 78.94,32.88 77.3,35.2 74.4,37.24 72.04,37.65 71.1,37.82 69.97,38.02 69.38,37.92 69.37,37.92 68.65,37.79 67.92,37.66 67.19,37.54 63.84,38.13 63.74,38.27 63.21,38.36 63.07,38.26 62.54,38.35 62.44,38.5 61.92,38.59 61.77,38.49 61.25,38.58 61.15,38.73 60.62,38.82 60.48,38.72 59.95,38.81 59.85,38.96 59.33,39.05 59.18,38.95 58.66,39.04 54.39,39.79 53.5,39.95 50.65,40.45 50.12,40.55 49.45,40.66 48.86,40.77 43.87,44.26 42.56,46.13 42.45,46.77 42.21,48.13 42.21,49.55 42.34,49.68 42.5,49.76 42.74,49.68 CN2.B20
PCIE_SLOT1_TXN2: length 74.5
  TOP w0.178: GF1.B59 71.65,5.83 71.3,6.18 71.3,7.48 74.78,11.34 78.71,19.24 79.56,22.87 80.9,30.49 80.33,33.74 78.83,35.88 74.95,38.6 74.89,38.64 69.67,39.56 67.71,39.22 67.11,39.11 65.66,39.37 65.47,39.63 64.77,39.75 64.51,39.57 63.81,39.69 63.62,39.96 62.92,40.08 62.66,39.89 60.02,40.36 59.5,40.45 56.13,41.04 55.61,41.14 47.97,46.49 46.98,47.18 46.32,48.13 46.25,48.53 46.25,49.58 46.34,49.68 46.5,49.76 46.74,49.68 CN2.B24
PCIE_SLOT1_TXN3: length 71.6
  TOP w0.178: GF1.B63 75.65,5.83 75.25,6.23 75.25,7.63 77.14,10.29 80.63,19.02 82.51,29.67 81.69,34.31 79.85,36.95 75.39,40.06 75.34,40.11 69.79,41.09 68.57,40.88 67.51,40.69 62.64,41.55 61.43,41.76 61.05,41.83 60.95,41.97 60.42,42.07 60.28,41.97 59.75,42.06 59.65,42.2 59.13,42.3 58.98,42.19 58.46,42.29 58.36,42.43 57.83,42.52 57.69,42.42 56.37,42.66 52.1,45.64 50.26,48.28 50.26,49.6 50.34,49.68 50.5,49.76 50.74,49.68 CN2.B28
PCIE_SLOT1_TXN4: length 66.3
  TOP w0.178: GF1.B67 79.65,5.83 79.25,6.23 79.25,7.7 82.6,18.24 83.27,22.06 84.34,28.1 83.17,34.73 80.88,38 75.9,41.49 70.54,42.43 65.9,43.25 65.8,43.4 65.27,43.49 65.13,43.39 64.6,43.48 64.5,43.62 63.98,43.72 63.83,43.62 63.31,43.71 63.21,43.85 62.68,43.95 62.54,43.84 62.01,43.94 57.19,47.31 56.23,48.28 56.23,49.57 56.34,49.68 56.5,49.76 56.74,49.68 CN2.B34
PCIE_SLOT1_TXN5: length 64.1
  TOP w0.178: GF1.B71 83.65,5.83 83.28,6.2 83.28,7.61 84.49,18.24 86.02,26.94 84.54,35.36 84.53,35.43 84.46,35.53 81.93,39.15 76.52,42.94 76.47,42.99 76.39,42.99 70.39,44.04 67.32,44.59 67.22,44.73 66.7,44.82 66.55,44.72 66.03,44.81 65.93,44.96 65.4,45.05 65.26,44.95 64.73,45.04 64.63,45.19 64.11,45.28 63.96,45.18 63.44,45.27 60.96,47 60.34,47.89 60.24,48.46 60.24,49.58 60.34,49.68 60.5,49.76 60.74,49.68 CN2.B38
PCIE_SLOT1_TXN6: length 61.7
  TOP w0.178: CN2.B42 64.74,49.68 64.5,49.76 64.34,49.68 64.25,49.59 64.25,48.91 64.39,48.14 65.01,47.26 66.42,46.27 70.58,45.54 71.11,45.44 71.25,45.54 71.78,45.45 71.88,45.31 72.41,45.21 72.55,45.32 73.07,45.22 73.18,45.08 73.7,44.99 73.85,45.09 74.37,44.99 74.47,44.85 77.11,44.39 82.95,40.29 85.89,36.1 87.55,26.75 86.91,19.04 87.28,7.79 87.28,6.2 87.65,5.83 GF1.B75
PCIE_SLOT1_TXN7: length 60.2
  TOP w0.178: GF1.B79 91.65,5.83 91.25,6.23 91.25,7.7 89.66,12.37 89.48,13.95 88.93,18.98 89.18,26.93 87.3,36.65 83.95,41.45 77.54,45.93 76.54,46.1 75.61,46.27 75.5,46.41 74.98,46.51 74.84,46.41 74.31,46.5 74.21,46.64 73.68,46.73 73.54,46.63 73.01,46.73 72.91,46.87 72.39,46.96 72.24,46.86 69.26,47.39 68.83,47.39 68.24,47.97 68.24,49.58 68.34,49.68 68.5,49.76 68.74,49.68 CN2.B46
PCIE_SLOT1_TXP0: length 82.7
  TOP w0.178: CN2.B14 37.44,49.68 37.68,49.76 37.84,49.68 37.96,49.56 37.96,47.48 39.77,45.68 39.77,44.27 40.49,43.23 42.42,41.89 42.45,41.71 42.88,41.41 43.06,41.44 43.49,41.13 43.52,40.96 43.96,40.65 44.13,40.68 44.57,40.38 44.6,40.2 45.04,39.9 45.21,39.93 46.76,38.84 55.04,37.38 57.62,36.93 60.97,36.34 65.04,35.62 66.02,35.62 70.22,36.21 73.64,35.61 76.15,33.85 77.42,32.03 77.61,30.95 77.61,30.94 77.61,30.5 75.03,20.97 70.01,13.8 67.69,11.76 67.65,11.73 63.59,8.44 63.03,7.45 63.03,6.35 62.65,5.97 GF1.B50
PCIE_SLOT1_TXP1: length 79.1
  TOP w0.178: CN2.B19 42.44,50.27 42.36,50.03 42.16,49.93 41.9,49.67 41.9,48.1 42.15,46.71 42.27,46.01 43.06,44.88 43.65,44.05 48.74,40.48 49.39,40.36 50.07,40.25 50.07,40.25 53.45,39.65 54.34,39.49 58.6,38.74 67.19,37.23 67.97,37.36 69.43,37.62 69.7,37.66 69.97,37.71 74.28,36.95 77.09,34.98 78.68,32.7 79.12,30.23 78.4,27.2 78.4,27.2 78.4,27.19 78.32,27 76.8,20.04 72.18,12.5 68.21,9.16 67.04,7.74 67.04,6.47 66.65,6.08 GF1.B54
PCIE_SLOT1_TXP2: length 74.5
  TOP w0.178: CN2.B23 46.44,50.27 46.36,50.03 46.16,49.93 45.94,49.71 45.94,48.48 45.94,48.48 46.03,48.01 46.76,46.96 47.89,46.17 55.49,40.85 67.11,38.8 68.11,38.98 68.11,38.98 69.67,39.25 74.77,38.35 74.78,38.35 78.61,35.66 80.04,33.62 80.59,30.49 79.26,22.93 78.43,19.34 74.53,11.52 74.32,11.29 71.17,7.78 71,7.61 71,6.18 70.65,5.83 GF1.B58
PCIE_SLOT1_TXP3: length 71.6
  TOP w0.178: CN2.B27 50.44,50.27 50.36,50.03 50.16,49.93 49.95,49.72 49.95,48.16 50.01,48.1 51.89,45.42 56.25,42.37 61.52,41.44 62.47,41.27 67.51,40.38 68.75,40.6 69.79,40.78 75.2,39.83 75.2,39.83 77.42,38.27 79.28,36.97 79.63,36.73 81.4,34.19 82.2,29.67 80.41,19.55 80.4,19.48 80.34,19.1 76.87,10.44 74.95,7.72 74.95,6.2 74.65,5.9 GF1.B62
PCIE_SLOT1_TXP4: length 66.3
  TOP w0.178: CN2.B33 56.44,50.27 56.36,50.03 56.16,49.93 55.92,49.69 55.92,48.15 56.96,47.12 56.97,47.09 61.89,43.65 70.48,42.13 75.78,41.2 80.66,37.78 82.88,34.62 84.03,28.1 82.3,18.31 78.95,7.75 78.95,6.26 78.65,5.97 GF1.B66
PCIE_SLOT1_TXP5: length 64.1
  TOP w0.178: CN2.B37 60.44,50.27 60.36,50.03 60.16,49.93 59.94,49.71 59.94,48.43 60.05,47.77 60.74,46.78 63.32,44.98 70.34,43.74 76.34,42.69 81.71,38.93 84.21,35.36 84.21,35.36 84.24,35.31 85.72,26.94 84.19,18.28 82.97,7.64 82.97,6.15 82.65,5.83 GF1.B70
PCIE_SLOT1_TXP6: length 61.7
  TOP w0.178: CN2.B41 64.44,50.27 64.36,50.03 64.16,49.93 63.95,49.72 63.95,48.94 63.94,48.91 64.1,48.02 64.79,47.04 66.3,45.98 70.53,45.23 76.99,44.1 82.73,40.08 85.6,35.98 87.25,26.74 86.6,19.05 86.97,7.78 86.97,6.21 86.65,5.89 GF1.B74
PCIE_SLOT1_TXP7: length 60.2
  TOP w0.178: GF1.B78 90.65,5.9 90.95,6.2 90.95,7.65 89.36,12.3 89.18,13.92 88.62,18.97 88.87,26.91 87.01,36.53 83.73,41.23 77.43,45.64 69.23,47.08 68.7,47.08 67.94,47.85 67.94,49.71 68.16,49.93 68.36,50.03 68.44,50.27 CN2.B45
PCIE_SLOT2_CPRSNT1_N: length 130.1
  TOP w0.178: CN3.B17 40.09,71.97 41.03,72.92 53.13,72.92 54.07,71.97 54.09,71.97 ; CN3.B31 54.09,71.97 ; 54.09,71.97 55.01,72.89 70.48,72.89 71.01,72.36 71.01,71.37 70.1,70.45 70.1,69.23 70.87,68.46 81.44,68.46 82.16,67.73 88.91,60.53 91.71,58.57 94.44,53.98 100.1,50.12 101.6,48.61 107.08,40.79 107.16,40.71 111.23,34.89 111.23,27.64 125.54,13.33 125.54,8.65 126,8.19 126,7.06 126.65,6.41 GF1.B114
PCIE_SLOT2_CPRSNT2_N: length 95
  TOP w0.178: CN3.B48 71.79,69.27 81.64,69.27 82.12,68.87 89.38,61.15 92.41,59.01 92.56,58.76 94.92,54.64 100.81,50.63 102.44,48.93 112.06,35.34 112.06,28.23 126.46,13.83 126.46,7.16 127.65,5.97 GF1.B115
PCIE_SLOT2_RXN0: length 108.2
  BOTTOM w0.178: GF1.A86 98.65,5.83 98.28,6.2 98.28,7.83 98.1,13.07 98.09,13.09 96.95,21.47 94.69,26.18 94.62,26.34 94.63,26.35 93.48,32.87 92.73,37.12 85.11,48 78.55,52.6 76.1,56.1 75.25,56.69 57.69,59.79 55.51,59.4 50.52,60.29 45.9,63.52 45.86,63.69 45.43,64 45.25,63.97 44.82,64.28 44.79,64.45 44.35,64.75 44.18,64.72 43.74,65.03 43.71,65.2 43.27,65.51 43.1,65.48 41.72,66.45 40.37,68.37 40.3,68.77 40.3,70.48 39.23,71.54 39.23,75.07 39.34,75.18 39.5,75.26 39.74,75.18 CN3.A17
PCIE_SLOT2_RXN1: length 105.3
  BOTTOM w0.178: GF1.A90 102.65,5.9 102.33,6.22 102.33,7.26 100.22,13.34 99.72,16.19 98.68,22.08 96.28,27.02 94.51,37.09 91.23,41.77 86.2,48.95 80.1,53.22 77.37,57.12 76.1,58.01 57.56,61.28 55.35,60.89 54.53,61.04 53.71,61.18 48.58,64.77 46.45,67.82 46.27,68.85 46.27,70.5 45.28,71.49 45.28,75.17 45.02,75.43 44.82,75.53 44.74,75.77 CN3.A22
PCIE_SLOT2_RXN2: length 105
  BOTTOM w0.178: GF1.A94 106.65,5.89 106.33,6.21 106.33,7.92 102.32,13.8 101.93,15.44 100.23,22.66 97.68,27.86 97.61,28.03 97.61,28.04 95.82,38.18 87.87,49.53 81.13,54.25 78.46,58.07 76.23,59.63 58.1,62.83 55.55,62.38 54.37,62.59 52.23,64.09 50.69,66.29 50.21,69.01 50.21,70.63 49.27,71.57 49.27,75.18 49.02,75.43 48.82,75.53 48.74,75.77 CN3.A26
PCIE_SLOT2_RXN3: length 102.3
  BOTTOM w0.178: GF1.A98 110.65,5.83 110.33,6.15 110.33,7.46 109.41,8.92 108.58,10.17 104.17,15.1 101.98,23.3 99.15,28.96 99.09,29.13 99.09,29.14 97.37,38.85 93.37,44.58 89.36,50.29 85.68,52.87 82.08,55.39 79.58,58.96 79.28,59.38 78.51,59.93 77.78,60.44 76.99,60.99 73.02,61.69 69.12,62.38 61.39,63.74 54.65,68.46 54.25,69.04 54.25,70.63 53.28,71.59 53.28,75.17 53.02,75.43 52.82,75.53 52.74,75.77 CN3.A30
PCIE_SLOT2_RXN4: length 100.2
  BOTTOM w0.178: CN3.A36 58.74,75.77 58.82,75.53 59.02,75.43 59.28,75.18 59.28,71.57 60.22,70.63 60.22,69.46 60.41,68.34 66.02,64.41 77.52,62.38 80.46,60.33 81.39,58.88 83.16,56.36 90.52,51.2 98.81,39.37 99.66,34.55 100.48,29.86 100.48,29.85 100.55,29.69 103.71,23.81 105.97,15.86 110.39,10.96 113.18,9.48 113.26,9.44 114.33,7.68 114.33,6.15 114.65,5.83 GF1.A102
PCIE_SLOT2_RXN5: length 99.2
  BOTTOM w0.178: GF1.A106 118.65,5.83 118.33,6.15 118.33,7.69 117.67,8.76 116.84,10.1 116.76,10.14 112.78,12.17 108.66,16.11 105.64,24.11 101.88,30.75 100.24,40.06 91.76,52.17 89.88,53.49 84.42,57.31 81.54,61.43 78.18,63.78 69.73,65.27 68.62,66.05 64.38,69.02 64.23,69.85 64.23,70.65 63.29,71.59 63.29,75.16 63.02,75.43 62.82,75.53 62.74,75.77 CN3.A40
PCIE_SLOT2_RXN6: length 98.8
  BOTTOM w0.178: GF1.A110 122.65,5.92 122.35,6.21 122.35,7.75 121.83,8.57 121.79,8.63 120.14,10.15 120.12,10.17 114.73,13.37 110.57,16.8 107.26,24.85 103.28,31.35 101.63,40.73 99.42,43.88 92.87,53.22 85.5,58.39 82.76,62.3 78.43,65.33 76.9,65.6 71.29,66.59 68.77,68.36 68.41,68.87 68.29,69.54 68.29,70.6 67.23,71.67 67.23,75.23 67.02,75.43 66.82,75.53 66.74,75.77 CN3.A44
PCIE_SLOT2_RXN7: length 97.4
  BOTTOM w0.178: GF1.A114 126.65,5.93 126.33,6.25 126.33,8.09 125.93,8.9 120.93,11.9 112.7,17.64 109.37,25.28 105.16,31.79 105.09,31.96 105.09,31.97 103.92,38.62 103.52,40.92 94.39,53.96 86.73,59.32 84.54,62.44 83.64,63.73 71.56,71.3 71.29,71.57 71.29,75.16 71.02,75.43 70.82,75.53 70.74,75.77 CN3.A48
PCIE_SLOT2_RXP0: length 108.2
  BOTTOM w0.178: GF1.A85 97.65,5.86 97.97,6.19 97.97,7.82 97.79,13.05 96.66,21.38 94.42,26.05 94.34,26.23 94.34,26.23 92.44,37 84.89,47.78 78.33,52.38 75.88,55.88 75.14,56.4 57.69,59.48 55.51,59.09 50.4,60 41.5,66.23 40.08,68.25 40,68.74 40,70.35 38.93,71.42 38.93,75.2 39.16,75.43 39.36,75.53 39.44,75.77 CN3.A16
PCIE_SLOT2_RXP1: length 105.3
  BOTTOM w0.178: CN3.A21 44.44,75.18 44.68,75.26 44.84,75.18 44.98,75.04 44.98,71.37 45.97,70.38 45.97,68.83 46.16,67.7 48.37,64.55 49.09,64.05 49.12,63.87 49.56,63.57 49.73,63.6 50.17,63.29 50.2,63.12 50.63,62.81 50.81,62.84 51.24,62.54 51.27,62.36 51.71,62.06 51.88,62.09 53.59,60.89 55.35,60.58 57.56,60.97 75.98,57.72 77.15,56.9 79.89,53 82.98,50.83 85.98,48.73 90.98,41.6 94.22,36.97 95.99,26.92 98.39,21.99 99.42,16.14 99.92,13.27 102.02,7.21 102.02,6.2 101.65,5.83 GF1.A89
PCIE_SLOT2_RXP2: length 104.9
  BOTTOM w0.178: CN3.A25 48.44,75.18 48.68,75.26 48.84,75.18 48.96,75.06 48.96,71.44 49.9,70.5 49.9,68.98 50.4,66.17 52.01,63.87 54.25,62.3 55.55,62.07 58.1,62.52 60.94,62.02 61.04,61.87 61.57,61.78 61.71,61.88 62.24,61.79 62.34,61.65 62.86,61.55 63.01,61.65 63.53,61.56 63.63,61.42 64.16,61.33 64.3,61.43 76.11,59.34 78.24,57.86 80.91,54.03 87.65,49.31 95.53,38.06 97.32,27.92 97.32,27.91 97.4,27.74 99.94,22.56 101.63,15.37 102.03,13.67 106.02,7.82 106.02,6.2 105.65,5.83 GF1.A93
PCIE_SLOT2_RXP3: length 102.3
  BOTTOM w0.178: GF1.A97 109.65,5.83 110.02,6.2 110.02,7.37 109.15,8.76 108.34,9.98 103.89,14.95 101.69,23.19 98.88,28.84 98.8,29.01 98.8,29.02 97.09,38.73 89.15,50.07 81.86,55.17 79.33,58.79 79.06,59.16 78.33,59.68 76.87,60.7 61.27,63.45 58.79,65.19 58.61,65.16 58.18,65.47 58.15,65.64 57.71,65.95 57.54,65.92 57.1,66.22 57.07,66.4 56.63,66.7 56.46,66.67 56.02,66.98 55.99,67.15 54.43,68.24 53.94,68.94 53.94,69.27 53.93,69.35 53.94,69.44 53.94,70.5 52.98,71.47 52.98,75.04 52.84,75.18 52.68,75.26 52.44,75.18 CN3.A29
PCIE_SLOT2_RXP4: length 100.2
  BOTTOM w0.178: GF1.A101 113.65,5.83 114.02,6.2 114.02,7.59 113.04,9.21 110.2,10.71 105.69,15.71 103.42,23.69 100.27,29.55 100.2,29.74 100.19,29.74 98.52,39.25 94.41,45.12 90.3,50.99 82.94,56.14 81.14,58.71 80.23,60.11 77.4,62.1 65.9,64.12 64.72,64.95 63.61,65.73 63.43,65.7 63,66 62.97,66.18 62.53,66.48 62.36,66.45 61.92,66.76 61.89,66.93 61.45,67.24 61.28,67.21 60.84,67.51 60.81,67.68 60.14,68.16 59.91,69.43 59.91,70.5 58.97,71.44 58.97,75.05 58.84,75.18 58.68,75.26 58.44,75.18 CN3.A35
PCIE_SLOT2_RXP5: length 99.2
  BOTTOM w0.178: GF1.A105 117.65,5.83 118.02,6.2 118.02,7.6 117.41,8.6 116.63,9.87 112.6,11.92 108.4,15.94 105.36,23.98 101.59,30.65 99.95,39.94 91.54,51.95 84.2,57.09 81.32,61.21 78.06,63.49 69.61,64.98 67.33,66.57 67.16,66.54 66.72,66.85 66.69,67.02 66.26,67.33 66.08,67.3 65.65,67.6 65.62,67.78 65.18,68.08 65,68.05 64.57,68.36 64.54,68.53 64.1,68.84 63.92,69.82 63.92,70.53 62.98,71.47 62.98,75.04 62.84,75.18 62.68,75.26 62.44,75.18 CN3.A39
PCIE_SLOT2_RXP6: length 98.8
  BOTTOM w0.178: CN3.A43 66.44,75.18 66.68,75.26 66.84,75.18 66.92,75.1 66.92,71.54 67.99,70.48 67.99,69.51 68.12,68.75 68.55,68.14 71.17,66.3 72.02,66.15 72.12,66.01 72.65,65.92 72.79,66.02 73.32,65.92 73.42,65.78 73.95,65.69 74.09,65.79 74.62,65.7 74.72,65.55 75.24,65.46 75.39,65.56 78.31,65.04 82.54,62.08 85.28,58.17 92.65,53.01 101.34,40.61 102.99,31.24 106.99,24.71 110.31,16.61 114.56,13.12 119.96,9.91 121.56,8.43 121.58,8.4 122.05,7.67 122.05,6.23 121.65,5.83 GF1.A109
PCIE_SLOT2_RXP7: length 97.4
  BOTTOM w0.178: CN3.A47 70.44,75.18 70.68,75.26 70.84,75.18 70.98,75.04 70.98,71.44 71.37,71.06 73.44,69.76 73.48,69.59 73.93,69.31 74.1,69.35 74.56,69.06 74.6,68.89 75.05,68.61 75.22,68.65 75.67,68.36 75.71,68.19 76.16,67.91 76.33,67.95 83.43,63.5 84.25,62.33 86.51,59.1 94.17,53.74 103.23,40.8 104.81,31.85 104.81,31.84 104.89,31.65 109.1,25.14 112.45,17.43 120.75,11.65 120.76,11.64 125.7,8.68 126.02,8.01 126.02,6.27 125.65,5.9 GF1.A113
PCIE_SLOT2_TXN0: length 104
  TOP w0.178: GF1.B84 96.65,5.91 96.33,6.23 96.33,7.4 97.1,11.29 97.66,18.21 97.66,18.69 97.66,18.69 97.24,21.05 97.2,21.28 95.91,28.6 94.5,36.59 90.42,42.43 85.08,46.45 82.3,50.42 73.46,56.61 53.9,60.03 48.39,61.96 42.29,65.54 38.29,69.54 38.29,70.66 38.02,70.93 37.82,71.03 37.74,71.27 CN3.B15
PCIE_SLOT2_TXN1: length 102.7
  TOP w0.178: CN3.B20 42.74,70.68 42.5,70.76 42.34,70.68 42.21,70.55 42.21,69.36 43.17,68.39 44.42,68.18 46.41,66.78 46.58,66.81 47.02,66.5 47.05,66.33 47.49,66.02 47.66,66.05 48.1,65.75 48.13,65.58 48.57,65.27 48.74,65.3 49.18,64.99 49.21,64.82 53.94,61.5 72.36,58.26 74.76,57.83 76.83,56.39 77.65,55.81 82.89,52.14 86.27,47.32 86.62,47.07 91.04,43.98 97.52,34.72 100.48,17.97 100.03,11.64 100.25,7.63 100.25,6.23 100.65,5.83 GF1.B88
PCIE_SLOT2_TXN2: length 101.8
  TOP w0.178: GF1.B92 104.65,5.91 104.35,6.21 104.35,7.69 104.22,9.05 104.21,9.09 103.43,12.66 103.28,18.21 103.28,18.39 103.28,18.39 100.77,32.61 100.36,33.2 92.12,44.98 87.29,48.36 83.8,53.34 83.72,53.42 75.51,59.17 68.52,60.4 61.4,61.66 61.3,61.8 60.77,61.89 60.63,61.79 60.1,61.88 60,62.03 59.48,62.12 59.33,62.02 58.81,62.11 58.71,62.26 58.18,62.35 58.04,62.25 54.55,62.86 53.01,63.94 51.13,65.82 50.18,66.77 50.18,66.95 49.8,67.32 49.63,67.32 49.25,67.7 48.3,68.65 46.78,68.65 46.25,69.18 46.25,70.58 46.34,70.68 46.5,70.76 46.74,70.68 CN3.B24
PCIE_SLOT2_TXN3: length 100.1
  TOP w0.178: GF1.B96 108.65,5.83 108.25,6.23 108.25,7.55 107.87,10.35 106.25,14.82 104.42,21.28 102.33,33.1 93.45,45.78 88.48,49.26 84.94,54.32 84.91,54.36 75.86,60.7 68.79,61.95 68.79,61.95 58.76,63.71 58.66,63.86 58.14,63.95 57.99,63.85 57.47,63.94 57.36,64.09 56.84,64.18 56.7,64.08 56.17,64.17 56.07,64.32 55.54,64.41 55.4,64.31 54.64,64.44 51.72,67.37 50.23,69.49 50.23,70.57 50.34,70.68 50.5,70.76 50.74,70.68 CN3.B28
PCIE_SLOT2_TXN4: length 96.9
  TOP w0.178: GF1.B100 112.65,5.83 112.3,6.18 112.3,7.59 112.1,10.68 112.04,11.69 109.52,16.92 105.71,23.85 104.02,33.39 94.76,46.62 89.73,50.15 86.76,54.39 86.09,55.35 76.6,61.99 76.59,62 76.53,62.03 62.85,64.44 59.93,66.49 59.87,66.8 59.29,67.21 58.98,67.15 58.4,67.56 58.34,67.87 57.76,68.28 57.45,68.22 56.69,68.76 56.23,69.41 56.23,70.57 56.34,70.68 56.5,70.76 56.74,70.68 CN3.B34
PCIE_SLOT2_TXN5: length 96.4
  TOP w0.178: CN3.B38 60.74,70.68 60.5,70.76 60.34,70.68 60.24,70.58 60.24,69.13 61.39,67.49 61.83,67.19 62,67.22 62.44,66.91 62.47,66.74 63.71,65.87 64.24,65.77 64.38,65.87 64.91,65.78 65.01,65.64 65.53,65.54 65.68,65.65 66.2,65.55 66.3,65.41 77.2,63.49 86.95,56.66 87.56,55.78 90.8,51.15 96.01,47.51 102.48,38.27 105.37,34.14 106.92,25.35 106.92,25.34 106.99,25.18 111.4,17.97 115.52,12.73 116.2,9.33 116.28,7.71 116.28,6.2 116.65,5.83 GF1.B104
PCIE_SLOT2_TXN6: length 95.1
  TOP w0.178: CN3.B42 64.74,70.68 64.5,70.76 64.34,70.68 64.25,70.59 64.25,69.49 65.19,68.15 67.28,66.68 70.5,66.12 70.64,66.22 71.16,66.13 71.27,65.98 71.79,65.89 71.94,65.99 72.46,65.9 72.56,65.75 73.09,65.66 73.23,65.76 73.76,65.67 73.86,65.52 73.88,65.52 77.74,64.84 77.79,64.8 88.42,57.36 88.66,57.02 92.07,52.15 96.89,48.77 106.76,34.67 108.29,26.04 113.03,18.85 117.99,13.26 118.05,13.2 119.12,11.42 119.13,11.39 120.27,7.83 120.27,6.23 120.65,5.84 GF1.B108
PCIE_SLOT2_TXN7: length 94.4
  TOP w0.178: GF1.B112 124.65,5.82 124.25,6.22 124.25,7.59 122.56,11.81 122.51,11.85 114.68,19.68 114.68,19.69 109.84,26.6 108.35,35.05 98.13,49.66 94.57,52.15 93.41,52.96 89.68,58.29 78.07,66.42 74.88,66.98 74.78,67.12 74.26,67.22 74.11,67.12 73.59,67.21 73.49,67.35 72.96,67.45 72.82,67.35 72.29,67.44 72.19,67.58 71.67,67.67 71.52,67.57 69.96,67.85 68.93,68.57 68.24,69.26 68.24,70.58 68.34,70.68 68.5,70.76 68.74,70.68 CN3.B46
PCIE_SLOT2_TXP0: length 104
  TOP w0.178: GF1.B83 95.65,5.83 96.02,6.2 96.02,7.43 96.8,11.33 97.35,18.22 97.35,18.69 97.35,18.69 94.21,36.47 92.48,38.96 92.21,39 91.81,39.58 91.85,39.85 91.44,40.43 91.18,40.47 90.78,41.06 90.82,41.32 90.19,42.21 84.86,46.23 82.08,50.2 73.34,56.32 53.82,59.73 48.26,61.68 42.1,65.3 42.08,65.32 37.99,69.41 37.99,70.53 37.84,70.68 37.76,70.72 37.68,70.76 37.44,70.68 CN3.B14
PCIE_SLOT2_TXP1: length 102.7
  TOP w0.178: CN3.B19 42.44,71.27 42.36,71.03 42.16,70.93 41.9,70.67 41.9,69.23 43.02,68.11 44.3,67.89 53.82,61.22 63.1,59.58 72.31,57.96 74.64,57.54 78.66,54.73 82.43,52.09 82.68,51.92 86.05,47.1 86.27,46.95 86.4,46.86 90.82,43.76 97.23,34.6 100.09,18.39 100.09,18.39 100.17,17.95 99.72,11.66 99.72,11.64 99.95,7.62 99.95,6.21 99.65,5.91 GF1.B87
PCIE_SLOT2_TXP2: length 101.8
  TOP w0.178: CN3.B23 46.44,71.27 46.36,71.03 46.16,70.93 45.94,70.71 45.94,69.06 46.65,68.34 48.18,68.34 49.03,67.49 52.81,63.71 54.43,62.57 68.47,60.1 75.39,58.88 83.52,53.18 83.56,53.15 87.07,48.14 91.9,44.76 100.17,32.93 100.48,32.49 100.48,32.49 102.97,18.39 102.97,18.39 102.97,18.2 103.12,12.62 103.91,9.03 103.92,9.01 104.05,7.68 104.05,6.23 103.65,5.83 GF1.B91
PCIE_SLOT2_TXP3: length 100.1
  TOP w0.178: GF1.B95 107.65,5.93 107.95,6.23 107.95,7.53 107.58,10.27 105.96,14.72 104.12,21.21 102.05,32.98 93.24,45.56 88.26,49.04 84.69,54.14 84.69,54.15 75.74,60.41 68.74,61.64 54.5,64.16 51.48,67.17 49.98,69.31 49.93,69.37 49.93,70.7 50.16,70.93 50.36,71.03 50.44,71.27 CN3.B27
PCIE_SLOT2_TXP4: length 96.9
  TOP w0.178: CN3.B33 56.44,71.27 56.36,71.03 56.16,70.93 55.92,70.69 55.92,69.32 56.47,68.54 62.73,64.15 76.43,61.74 85.87,55.13 86.33,54.48 89.51,49.93 94.54,46.41 103.74,33.27 105.42,23.75 109.25,16.78 111.74,11.61 111.8,10.66 112,7.58 112,6.18 111.65,5.83 GF1.B99
PCIE_SLOT2_TXP5: length 96.4
  TOP w0.178: GF1.B103 115.65,5.83 115.97,6.15 115.97,7.7 115.9,9.29 115.23,12.6 111.15,17.79 106.72,25.04 106.64,25.23 106.64,25.23 106.63,25.23 105.08,34.02 95.79,47.29 90.59,50.93 87.25,55.7 86.73,56.44 77.08,63.2 63.59,65.58 61.17,67.27 59.94,69.04 59.94,70.71 60.07,70.85 60.16,70.93 60.36,71.03 60.44,71.27 CN3.B37
PCIE_SLOT2_TXP6: length 95.1
  TOP w0.178: CN3.B41 64.44,71.27 64.36,71.03 64.16,70.93 63.95,70.72 63.95,69.39 64.98,67.93 67.16,66.4 73.82,65.22 73.82,65.22 77.62,64.55 88.2,57.14 91.85,51.93 96.67,48.56 106.48,34.55 108,25.93 112.79,18.67 117.76,13.06 117.8,13.02 118.84,11.29 119.96,7.78 119.96,6.23 119.65,5.92 GF1.B107
PCIE_SLOT2_TXP7: length 94.4
  TOP w0.178: GF1.B111 123.65,5.93 123.95,6.23 123.95,7.53 122.3,11.64 114.47,19.47 114.46,19.47 109.56,26.48 108.07,34.93 97.91,49.44 94.4,51.9 94.39,51.9 93.19,52.74 89.46,58.07 77.95,66.13 69.84,67.56 68.73,68.34 67.94,69.13 67.94,70.71 68.16,70.93 68.36,71.03 68.44,71.27 CN3.B45
PCIE_SMCLK: length 50.5
  TOP w0.178: U10.18 3.26,46.5 3.15,46.39 2.67,46.39 1.83,45.55 1.83,40.24 13.31,28.76 13.31,14.23 16,11.54 16,6.23 15.65,5.88 GF1.B5
PCIE_SMCLK0: length 9.6
  TOP w0.178: U10.6 10.84,48.45 10.91,48.38 12.92,48.38 15.65,45.65 15.65,44.64 R18.2 15.97,44.32 RE1.2
PCIE_SMCLK1: length 8.4
  TOP w0.178: RE6.2 16.13,48.68 R19.2 15.84,48.42 14.91,48.42 13.04,50.29 11,50.29 10.89,50.4 U10.9
PCIE_SMCLK2: length 34.8
  TOP w0.178: RE12.2 25.42,65.31 v1(25.54,65.19) ; v1(12.89,60.55) 12.57,60.23 12.57,59.06 10.36,56.85 9.14,56.85 6.88,54.58 6.88,53.94 7.17,53.65 R20.2 6.88,52.91 6.88,50.97 5.77,49.87 5.14,49.87 5.02,49.75 U10.13
  BOTTOM w0.178: v1(25.54,65.19) 25.75,65.39 25.75,65.75 25.59,65.91 17.25,65.91 ; 17.25,65.91 16.22,65.91 12.57,62.26 12.57,60.87 v1(12.89,60.55) ; 17.25,65.91 v2(17.25,65.58)
PCIE_SMDAT: length 49.7
  TOP w0.178: GF1.B6 16.65,5.93 16.43,6.15 16.43,11.72 13.74,14.41 13.74,28.94 2.26,40.42 2.26,45.37 2.84,45.96 3.15,45.96 3.26,45.85 U10.19
PCIE_SMDAT0: length 8.9
  TOP w0.178: RE7.2 14.93,43.25 R21.2 15.21,44.62 15.21,45.47 12.74,47.95 10.99,47.95 10.85,47.8 U10.5
PCIE_SMDAT1: length 8.4
  TOP w0.178: U10.8 10.89,49.75 11,49.86 12.86,49.86 14.73,47.99 15.81,47.99 R22.2 16.13,47.67 RE8.2
PCIE_SMDAT2: length 35.5
  TOP w0.178: v1(26.46,65.22) 26.56,65.32 RE13.2 ; U10.12 5.05,50.4 5.15,50.3 5.59,50.3 6.44,51.15 6.44,52.91 R23.2 6.15,53.65 6.44,53.94 6.44,54.76 8.96,57.28 10.18,57.28 12.14,59.24 12.14,60.22 v1(11.82,60.55)
  BOTTOM w0.178: 20.73,66.34 16.04,66.34 12.14,62.44 12.14,60.87 v1(11.82,60.55) ; 20.73,66.34 25.77,66.34 26.18,65.93 26.18,65.5 v1(26.46,65.22) ; 20.73,66.34 v2(20.73,66.68)
PCIE_WAKE_N: length 89.1
  TOP w0.178: 33.93,28.94 35.47,30.47 35.47,31.93 34.14,33.25 34.14,35.01 35.07,35.93 35.07,45.33 33.38,47.02 33.38,49.69 CN2.B11 32.09,51.79 31.22,52.66 31.22,53.99 33.94,56.71 38.01,56.71 40.56,59.27 40.56,61.65 37.8,64.42 36.93,64.42 36.12,65.24 36.12,66.84 34.54,68.41 34.54,69.15 32.09,71.6 CN3.B11 ; 33.93,28.94 33.13,28.94 CN1.B11 ; 33.93,28.94 33.93,20.84 21.58,8.48 21.58,6.35 21.65,6.28 GF1.B11
PERST_O_1_R: length 2.9
  TOP w0.178: U8.1 22.44,22.38 23.07,21.74 R37.2 23.07,20.14 R3.2
PERST_O_2_R: length 5.2
  TOP w0.178: U9.1 11.55,75.54 11.94,75.93 12.78,75.93 14.11,74.59 R4.2 R36.2
PERST_P12V_MB_Y_N: length 4.9
  TOP w0.178: R41.1 24.19,24.58 23.39,25.38 21.82,25.38 21.49,25.05 21.49,24.26 21.28,24.06 U8.4
PERST_P12V_R_N: length 24.6
  TOP w0.178: R42.2 R41.2 25.25,24.42 28.14,27.31 28.14,28.43 27.1,29.47 27.1,30.41 26.64,30.87 21.72,30.87 20.42,32.16 20.42,33.99 19.18,35.24 17.37,35.24 16.37,36.24 U13.1
PERST_P12V_Y_N: length 59.5
  TOP w0.178: v1(18.21,23.58) 18.38,23.41 U8.2 22.52,23.33 R42.1 ; v1(13.26,53.12) 13.26,56.95 13.77,57.46 13.77,68.64 10.25,72.16 U9.4
  BOTTOM w0.178: v1(18.21,23.58) 16.13,25.66 16.13,42.3 13.26,45.17 v1(13.26,53.12)
PERST_SLOT0_N: length 16.1
  TOP w0.178: R39.2 19.88,37.51 21.82,35.57 31.34,35.57 32.09,34.82 CN1.A11
PERST_SLOT1_N: length 19.3
  TOP w0.178: R38.2 20.69,40.46 v1(21.46,41.23)
  BOTTOM w0.178: v1(21.46,41.23) 22.76,42.53 25.1,42.53 30.07,47.51 30.07,49.31 31.09,50.33 31.09,52.47 CN2.A11
PERST_SLOT2_N: length 52.5
  TOP w0.178: CN3.A11 32.09,74.1 31.09,73.1 31.09,71.66 33.91,68.84 33.91,68.03 35.36,66.58 35.36,64.73 36.45,63.63 37.54,63.63 39.7,61.48 39.7,59.55 37.57,57.41 33.68,57.41 32.97,56.7 30.71,56.7 30.07,56.07 30.07,55.08 29.11,54.11 29.11,50.55 28.09,49.54 28.09,47.1 25.98,44.99 22.81,44.99 19.46,41.64 R40.2
PERST_SLOT_N: length 4.5
  TOP w0.178: U13.4 17.67,39.16 18.43,38.4 R39.1 R40.1 19.48,39.57 R38.1
RESET_O_1: length 1.5
  TOP w0.178: U1.2 22.16,19.39 R3.1
RESET_O_2: length 1.6
  TOP w0.178: U2.2 15.43,75.48 R4.1
RESET_P12V_IN: length 5.2
  TOP w0.178: R5.2 R24.1 C37.1 15.78,71.95 U2.3
